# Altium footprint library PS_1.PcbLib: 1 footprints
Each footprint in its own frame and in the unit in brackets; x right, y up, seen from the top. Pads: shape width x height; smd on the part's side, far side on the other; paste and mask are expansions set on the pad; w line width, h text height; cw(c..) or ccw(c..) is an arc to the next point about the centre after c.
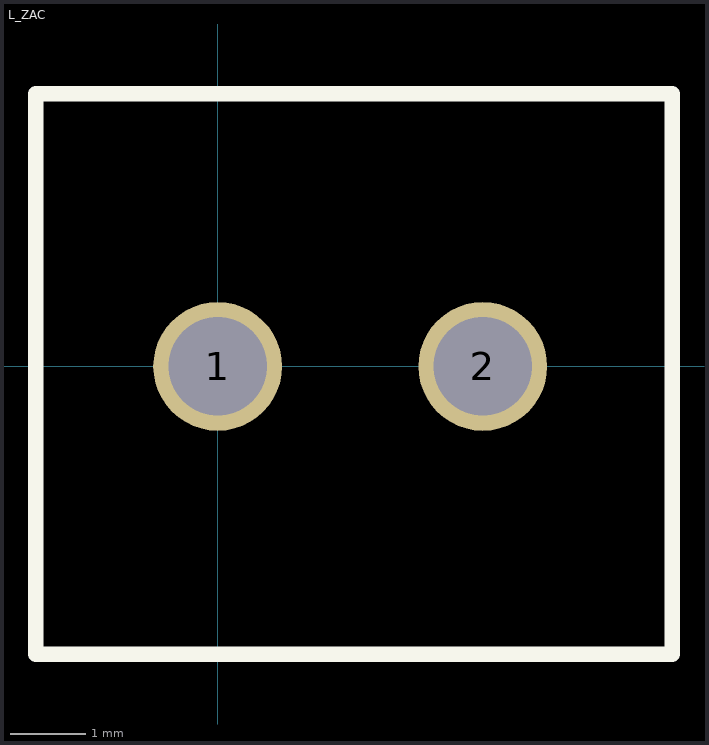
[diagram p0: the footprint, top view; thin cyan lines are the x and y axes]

## L_ZAC [mm]
pads (2):
  round 1.7 hole 1.3: 1(0,0) 2(3.5,0)
Top Overlay:
  lines w0.2: -2.4,-3.8 -2.4,3.6 6,3.6 6,-3.8 -2.4,-3.8
3D body: height 8.5, standoff -4, extent -2.2,-3.6 5.8,3.4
